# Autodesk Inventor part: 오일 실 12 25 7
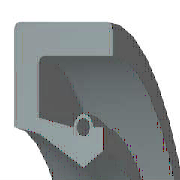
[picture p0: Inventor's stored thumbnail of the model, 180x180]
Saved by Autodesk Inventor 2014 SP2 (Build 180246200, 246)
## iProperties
IsCustomPart: 1
Created: 2012-02
Part Number: 오일 실 12 25 7
Material: 고무
Description: 오일-실
Document SubType Name: Modeling
Standard: KS B 2804
Designer: mduedu
Standards Organization: KS
Language: ko-KR
Size Designation: S - 12 25 7
Categories: <MemberInstance><Categories><Category DisplayName="샤프트 부품" InternalName="7f7aeb1f-a693-4053-b835-cee3144e0d98" Mnemonic="SHFT"><Category DisplayName="실링" Intern
Density: 0.93 g/cm^3
Appearance: 고무 - 검은색 - 버전 1.1
Mass: 1.26338 g
Surface Area: 20.8889 cm^2
Volume: 1.35847 cm^3
Author: mduedu
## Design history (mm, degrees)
revolve "본체" stored, may be unused: angle "d17" = 90 deg
revolve "스프링1" stored, may be unused: angle "d18" = 90 deg
body "Solid1"
sketch "스케치1"
  geometry: L1 (0, 12.5)-(7, 12.5); L2 (7, 12.5)-(7, 11.25); L3 (7, 11.25)-(1.75, 11.25); L4 (0, 12.5)-(0, 8.1); L5 (0, 8.1)-(1.75, 7.75); L6 (1.75, 7.75)-(4.9, 6); L7 (4.9, 6)-(0, 6); L8 (6.3, 6.875)-(6.3, 8.1); L9 (0, 0)-(9.586, 0) reference; L10 (4.9, 6)-(6.3, 6.875); L11 (0, 18)-(0, -3) reference; L12 (-1.917, 0)-(11.503, 0) reference; L13 (4.2, 8.1)-(1.75, 8.59); L14 (1.75, 8.59)-(1.75, 11.25); L15 (6.3, 8.1)-(5.6, 8.1); C1 r 0.455 at (4.9, 8.1); A1 r 0.7 centre (4.9, 8.1) between (5.6, 8.1) and (4.2, 8.1)
  constraints: 26 end point, 5 horizontal alignment, 4 perpendicular, 2 centre point, 2 collinear, 2 horizontal, 2 parallel, 2 point on circle, 2 point on line, 2 vertical alignment, 1 coincident
  dimensions: "d0" = 25 diameter of L1 L9 (= SD2); "d1" = 13.75 diameter of L8.start L9 (= ABDM); "d2" = 1.25 distance of L1.end L2.end (computed from SD); "d3" = 0.91 diameter of C1 (= SPDI); "d4" = 1.4 diameter of A1 (= SPDA); "d5" = 12 diameter of L6.end L9 (= NND); "d6" = 15.5 diameter of L5.end L9 (= TKDM); "d7" = 16.2 diameter of L4.end L9 (= HLDM); "d8" = 4.9 distance from line of C1.centre L4 (= SPDST); "d9" = 6.3 distance between parallel lines of L8 L4 (= SDI); "d10" = 7 distance between parallel lines of L2 L4 (= SWDT); "d12" = 1.75 distance between parallel lines of L14 L4 (= SD)
fillet "모깎기1" dims "d11" = 0.3 (= RR)
other parameters: "SD2" = 25 [user parameter; used in 1 equation term], "SWDT" = 7 [user parameter; used in 1 equation term], "RR" = 0.3 [user parameter; used in 1 equation term], "SD" = 1.75 [user parameter; used in 2 equation terms], "NND" = 12 [user parameter; used in 1 equation term], "SPDA" = 1.4 [user parameter; used in 1 equation term], "SPDI" = 0.91 [user parameter; used in 1 equation term], "TKDM" = 15.5 [user parameter; used in 1 equation term], "HLDM" = 16.2 [user parameter; used in 1 equation term], "ABDM" = 13.75 [user parameter; used in 1 equation term], "SDI" = 6.3 [user parameter; used in 1 equation term], "SPDST" = 4.9 [user parameter; used in 1 equation term], "d13" = 0, "d14" = 0, "d15" = 0, "LAB" = 0.35 [user parameter]
